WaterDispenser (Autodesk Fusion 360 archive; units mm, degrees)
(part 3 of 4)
sketch "Sketch5" plane through (0, 0, -156.7) normal (0, 0, -1) x axis (-1, 0, 0)
  line L1 (-105.7, 139.3) -> (-100, 139.3)
  line L2 (-105.7, 149.3) -> (-105.7, 139.3)
  line L3 (-100, 149.3) -> (-105.7, 149.3)
  line L4 (-100, 159.3) -> (-100, 149.3)
  line L5 (-105.7, 159.3) -> (-100, 159.3)
  line L6 (-105.7, 169.3) -> (-105.7, 159.3)
  line L7 (-100, 169.3) -> (-105.7, 169.3)
  line L8 (-100, 179.3) -> (-100, 169.3)
  line L9 (-105.7, 179.3) -> (-100, 179.3)
  line L10 (-105.7, 189.3) -> (-105.7, 179.3)
  line L11 (-100, 189.3) -> (-105.7, 189.3)
  line L12 (-100, 199.3) -> (-100, 189.3)
  line L13 (-105.7, 199.3) -> (-100, 199.3)
  line L14 (-105.7, 209.3) -> (-105.7, 199.3)
  line L15 (-100, 209.3) -> (-105.7, 209.3)
  line L16 (-100, 219.3) -> (-100, 209.3)
  line L17 (-105.7, 219.3) -> (-100, 219.3)
  line L18 (-105.7, 229.3) -> (-105.7, 219.3)
  line L19 (-100, 229.3) -> (-105.7, 229.3)
  line L20 (-100, 245) -> (-100, 229.3)
  line L21 (-121, 245) -> (-100, 245)
  line L22 (-121, 239.3) -> (-121, 245)
  line L23 (-131, 239.3) -> (-121, 239.3)
  line L24 (-131, 245) -> (-131, 239.3)
  line L25 (-141, 245) -> (-131, 245)
  line L26 (-141, 239.3) -> (-141, 245)
  line L27 (-151, 239.3) -> (-141, 239.3)
  line L28 (-151, 245) -> (-151, 239.3)
  line L29 (-161, 245) -> (-151, 245)
  line L30 (-161, 239.3) -> (-161, 245)
  line L31 (-171, 239.3) -> (-161, 239.3)
  line L32 (-171, 245) -> (-171, 239.3)
  line L33 (-181, 245) -> (-171, 245)
  line L34 (-181, 239.3) -> (-181, 245)
  line L35 (-191, 239.3) -> (-181, 239.3)
  line L36 (-191, 245) -> (-191, 239.3)
  line L37 (-201, 245) -> (-191, 245)
  line L38 (-201, 230) -> (-201, 245)
  line L39 (-206.7, 230) -> (-201, 230)
  line L40 (-206.7, 220) -> (-206.7, 230)
  line L41 (-201, 220) -> (-206.7, 220)
  line L42 (-201, 210) -> (-201, 220)
  line L43 (-206.7, 210) -> (-201, 210)
  line L44 (-206.7, 200) -> (-206.7, 210)
  line L45 (-201, 200) -> (-206.7, 200)
  line L46 (-201, 190) -> (-201, 200)
  line L47 (-206.7, 190) -> (-201, 190)
  line L48 (-206.7, 180) -> (-206.7, 190)
  line L49 (-201, 180) -> (-206.7, 180)
  line L50 (-201, 170) -> (-201, 180)
  line L51 (-206.7, 170) -> (-201, 170)
  line L52 (-206.7, 160) -> (-206.7, 170)
  line L53 (-201, 160) -> (-206.7, 160)
  line L54 (-201, 150) -> (-201, 160)
  line L55 (-206.7, 150) -> (-201, 150)
  line L56 (-206.7, 140) -> (-206.7, 150)
  line L57 (-201, 140) -> (-206.7, 140)
  line L58 (-201, 130) -> (-201, 140)
  line L59 (-206.7, 130) -> (-201, 130)
  line L60 (-206.7, 120) -> (-206.7, 130)
  line L61 (-201, 120) -> (-206.7, 120)
  line L62 (-201, 110) -> (-201, 120)
  line L63 (-206.7, 110) -> (-201, 110)
  line L64 (-206.7, 100) -> (-206.7, 110)
  line L65 (-201, 100) -> (-206.7, 100)
  line L66 (-201, 90) -> (-201, 100)
  line L67 (-206.7, 90) -> (-201, 90)
  line L68 (-206.7, 80) -> (-206.7, 90)
  line L69 (-201, 80) -> (-206.7, 80)
  line L70 (-201, 70) -> (-201, 80)
  line L71 (-206.7, 70) -> (-201, 70)
  line L72 (-206.7, 60) -> (-206.7, 70)
  line L73 (-201, 60) -> (-206.7, 60)
  line L74 (-201, 50) -> (-201, 60)
  line L75 (-206.7, 50) -> (-201, 50)
  line L76 (-206.7, 40) -> (-206.7, 50)
  line L77 (-201, 40) -> (-206.7, 40)
  line L78 (-201, 30) -> (-201, 40)
  line L79 (-206.7, 30) -> (-201, 30)
  line L80 (-206.7, 20) -> (-206.7, 30)
  line L81 (-201, 20) -> (-206.7, 20)
  line L82 (-201, 10) -> (-201, 20)
  line L83 (-206.7, 10) -> (-201, 10)
  line L84 (-206.7, -5.7) -> (-206.7, 10)
  line L85 (-199, -5.7) -> (-206.7, -5.7)
  line L86 (-199, 0) -> (-199, -5.7)
  line L87 (-189, 0) -> (-199, 0)
  line L88 (-189, -5.7) -> (-189, 0)
  line L89 (-179, -5.7) -> (-189, -5.7)
  line L90 (-179, 0) -> (-179, -5.7)
  line L91 (-169, 0) -> (-179, 0)
  line L92 (-169, -5.7) -> (-169, 0)
  line L93 (-159, -5.7) -> (-169, -5.7)
  line L94 (-159, 0) -> (-159, -5.7)
  line L95 (-149, 0) -> (-159, 0)
  line L96 (-149, -5.7) -> (-149, 0)
  line L97 (-139, -5.7) -> (-149, -5.7)
  line L98 (-139, 0) -> (-139, -5.7)
  line L99 (-129, 0) -> (-139, 0)
  line L100 (-129, -5.7) -> (-129, 0)
  line L101 (-119, -5.7) -> (-129, -5.7)
  line L102 (-119, 0) -> (-119, -5.7)
  line L103 (-109, 0) -> (-119, 0)
  line L104 (-109, -5.7) -> (-109, 0)
  line L105 (-99, -5.7) -> (-109, -5.7)
  line L106 (-99, 0) -> (-99, -5.7)
  line L107 (-89, 0) -> (-99, 0)
  line L108 (-89, -5.7) -> (-89, 0)
  line L109 (-79, -5.7) -> (-89, -5.7)
  line L110 (-79, 0) -> (-79, -5.7)
  line L111 (-69, 0) -> (-79, 0)
  line L112 (-69, -5.7) -> (-69, 0)
  line L113 (-59, -5.7) -> (-69, -5.7)
  line L114 (-59, 0) -> (-59, -5.7)
  line L115 (-49, 0) -> (-59, 0)
  line L116 (-49, -5.7) -> (-49, 0)
  line L117 (-39, -5.7) -> (-49, -5.7)
  line L118 (-39, 0) -> (-39, -5.7)
  line L119 (-29, 0) -> (-39, 0)
  line L120 (-29, -5.7) -> (-29, 0)
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extrude "Extrude9" cut sketch "Sketch5" to an object
sketch "Sketch3" plane through (206.7, 0, 0) normal (1, 0, 0) x axis (0, 0, -1)
  line L1 (59, -5.7) -> (59, 0)
  line L2 (69, -5.7) -> (59, -5.7)
  line L3 (69, 0) -> (69, -5.7)
  line L4 (75, 0) -> (69, 0)
  line L5 (75, 239.3) -> (75, 0)
  line L6 (69, 239.3) -> (75, 239.3)
  line L7 (69, 245) -> (69, 239.3)
  line L8 (59, 245) -> (69, 245)
  line L9 (59, 239.3) -> (59, 245)
  line L10 (49, 239.3) -> (59, 239.3)
  line L11 (49, 245) -> (49, 239.3)
  line L12 (39, 245) -> (49, 245)
  line L13 (39, 239.3) -> (39, 245)
  line L14 (29, 239.3) -> (39, 239.3)
  line L15 (29, 245) -> (29, 239.3)
  line L16 (19, 245) -> (29, 245)
  line L17 (19, 239.3) -> (19, 245)
  line L18 (9, 239.3) -> (19, 239.3)
  line L19 (9, 245) -> (9, 239.3)
  line L20 (-6.7, 245) -> (9, 245)
  line L21 (-6.7, 230) -> (-6.7, 245)
  line L22 (-1, 230) -> (-6.7, 230)
  line L23 (-1, 220) -> (-1, 230)
  line L24 (-6.7, 220) -> (-1, 220)
  line L25 (-6.7, 210) -> (-6.7, 220)
  line L26 (-1, 210) -> (-6.7, 210)
  line L27 (-1, 200) -> (-1, 210)
  line L28 (-6.7, 200) -> (-1, 200)
  line L29 (-6.7, 190) -> (-6.7, 200)
  line L30 (-1, 190) -> (-6.7, 190)
  line L31 (-1, 180) -> (-1, 190)
  line L32 (-6.7, 180) -> (-1, 180)
  line L33 (-6.7, 170) -> (-6.7, 180)
  line L34 (-1, 170) -> (-6.7, 170)
  line L35 (-1, 160) -> (-1, 170)
  line L36 (-6.7, 160) -> (-1, 160)
  line L37 (-6.7, 150) -> (-6.7, 160)
  line L38 (-1, 150) -> (-6.7, 150)
  line L39 (-1, 140) -> (-1, 150)
  line L40 (-6.7, 140) -> (-1, 140)
  line L41 (-6.7, 130) -> (-6.7, 140)
  line L42 (-1, 130) -> (-6.7, 130)
  line L43 (-1, 120) -> (-1, 130)
  line L44 (-6.7, 120) -> (-1, 120)
  line L45 (-6.7, 110) -> (-6.7, 120)
  line L46 (-1, 110) -> (-6.7, 110)
  line L47 (-1, 100) -> (-1, 110)
  line L48 (-6.7, 100) -> (-1, 100)
  line L49 (-6.7, 90) -> (-6.7, 100)
  line L50 (-1, 90) -> (-6.7, 90)
  line L51 (-1, 80) -> (-1, 90)
  line L52 (-6.7, 80) -> (-1, 80)
  line L53 (-6.7, 70) -> (-6.7, 80)
  line L54 (-1, 70) -> (-6.7, 70)
  line L55 (-1, 60) -> (-1, 70)
  line L56 (-6.7, 60) -> (-1, 60)
  line L57 (-6.7, 50) -> (-6.7, 60)
  line L58 (-1, 50) -> (-6.7, 50)
  line L59 (-1, 40) -> (-1, 50)
  line L60 (-6.7, 40) -> (-1, 40)
  line L61 (-6.7, 30) -> (-6.7, 40)
  line L62 (-1, 30) -> (-6.7, 30)
  line L63 (-1, 20) -> (-1, 30)
  line L64 (-6.7, 20) -> (-1, 20)
  line L65 (-6.7, 10) -> (-6.7, 20)
  line L66 (-1, 10) -> (-6.7, 10)
  line L67 (-1, -5.7) -> (-1, 10)
  line L68 (9, -5.7) -> (-1, -5.7)
  line L69 (9, 0) -> (9, -5.7)
  line L70 (19, 0) -> (9, 0)
  line L71 (19, -5.7) -> (19, 0)
  line L72 (29, -5.7) -> (19, -5.7)
  line L73 (29, 0) -> (29, -5.7)
  line L74 (39, 0) -> (29, 0)
  line L75 (39, -5.7) -> (39, 0)
  line L76 (49, -5.7) -> (39, -5.7)
  line L77 (49, 0) -> (49, -5.7)
  line L78 (59, 0) -> (49, 0)
  line L79 (18.25, 199.3) -> (18.25, 205)
  line L80 (43.25, 199.3) -> (18.25, 199.3)
  line L81 (43.25, 205) -> (43.25, 199.3)
  line L82 (18.25, 205) -> (43.25, 205)
  line L83 (62.5, 199.3) -> (62.5, 205)
  line L84 (75, 199.3) -> (62.5, 199.3)
  line L85 (75, 205) -> (75, 199.3)
  line L86 (62.5, 205) -> (75, 205)
  line L87 (87.5, 205) -> (87.5, 199.3)
  line L88 (75, 205) -> (87.5, 205)
  line L89 (75, 199.3) -> (75, 205)
  line L90 (87.5, 199.3) -> (75, 199.3)
  line L91 (131.75, 205) -> (131.75, 199.3)
  line L92 (106.75, 205) -> (131.75, 205)
  line L93 (106.75, 199.3) -> (106.75, 205)
  line L94 (131.75, 199.3) -> (106.75, 199.3)
extrude "Extrude3" cut sketch "Sketch3" profile of L5 L79 L80 L81 L82 L83 L84 L85 L86 L87 L88 L89 L90 L91 L92 L93 L94 to an object
sketch "Sketch6" plane through (0, 199.3, 0) normal (0, -1, 0) x axis (1, 0, 0)
  line L1 (164.675, -156.7) -> (164.675, -151)
  line L2 (189.675, -156.7) -> (164.675, -156.7)
  line L3 (189.675, -151) -> (189.675, -156.7)
  line L4 (201, -151) -> (189.675, -151)
  line L5 (201, -131.75) -> (201, -151)
  line L6 (206.7, -131.75) -> (201, -131.75)
  line L7 (206.7, -106.75) -> (206.7, -131.75)
  line L8 (201, -106.75) -> (206.7, -106.75)
  line L9 (201, -87.5) -> (201, -106.75)
  line L10 (206.7, -87.5) -> (201, -87.5)
  line L11 (206.7, -75) -> (206.7, -87.5)
  line L12 (105.7, -75) -> (206.7, -75)
  line L13 (105.7, -151) -> (105.7, -75)
  line L14 (164.675, -151) -> (105.7, -151)
  circle C1 centre (187.05, -137.05) radius 4.95
sketch "Sketch4" plane through (0, 199.3, 0) normal (0, -1, 0) x axis (1, 0, 0)
  line L1 (164.675, -156.7) -> (164.675, -151)
  line L2 (189.675, -156.7) -> (164.675, -156.7)
  line L3 (189.675, -151) -> (189.675, -156.7)
  line L4 (201, -151) -> (189.675, -151)
  line L5 (201, -131.75) -> (201, -151)
  line L6 (206.7, -131.75) -> (201, -131.75)
  line L7 (206.7, -106.75) -> (206.7, -131.75)
  line L8 (201, -106.75) -> (206.7, -106.75)
  line L9 (201, -87.5) -> (201, -106.75)
  line L10 (206.7, -87.5) -> (201, -87.5)
  line L11 (206.7, -75) -> (206.7, -87.5)
  line L12 (105.7, -75) -> (206.7, -75)
  line L13 (105.7, -151) -> (105.7, -75)
  line L14 (164.675, -151) -> (105.7, -151)
  circle C1 centre (187.05, -137.05) radius 4.95
extrude "Extrude3" cut sketch "Sketch4" profile of C1 to an object
sketch "Sketch7" plane through (195, 0, 0) normal (-1, 0, 0) x axis (0, 0, 1)
  line L1 (-137.05, 35) -> (-126, 35)
  line L2 (-145, 35) -> (-137.05, 35)
  line L3 (-145, 0) -> (-145, 35)
  line L4 (-5, 0) -> (-145, 0)
  line L5 (-5, 15) -> (-5, 0)
  line L6 (-126, 15) -> (-5, 15)
  line L7 (-126, 35) -> (-126, 15)
  line L8 (-126, 15) -> (-5, 15)
  line L9 (-145, 0) -> (-5, 0)
  line L10 (-5, 15) -> (-5, 0)
  line L11 (-25, 0) -> (-25, 15)
  circle C1 centre (-25, 7.5) radius 5
  point P13 (-25, 15)
  point P15 (-25, 7.5)
  point P14 (-25, 0)
  vertical L11
  coincident L8 P13
  midpoint L11 P15
  dimension "d360" distance P13 P14 = 15
  dimension "d363" distance L5 L11 = 20 (= "AcDistanceHole")
  dimension "d364" diameter C1 = 10 (= "AcHoleDiameter")
extrude "Extrude17" cut sketch "Sketch7" profile of L11 C1 against normal blind 11.7
combine "Combine4"
chamfer "Chamfer6" distance 8 distance 6
fillet "Fillet22" radius 2
sketch "Sketch14" plane through (0, 0, 0) normal (0, -1, 0) x axis (1, 0, 0)
  line L1 (0, -150) -> (0, 0)
  line L2 (200, -150) -> (0, -150)
  line L3 (200, 0) -> (200, -150)
  line L4 (0, 0) -> (200, 0)
  line L5 (195, -5) -> (5, -5)
  line L6 (195, -145) -> (195, -5)
  line L7 (5, -145) -> (195, -145)
  line L8 (5, -5) -> (5, -145)
  circle C1 centre (0, -150) radius 15
  circle C2 centre (0, 0) radius 15
  circle C3 centre (200, 0) radius 15
  circle C4 centre (200, -150) radius 15
  point P3 (0, -150)
  point P10 (0, -150)
  point P1 (0, 0)
  point P11 (0, 0)
  point P5 (200, 0)
  point P12 (200, 0)
  point P4 (200, -150)
  point P13 (200, -150)
  coincident P3 P10
  coincident P1 P11
  coincident P5 P12
  coincident P4 P13
  dimension "d374" diameter C1 = 30
  dimension "d375" diameter C2 = 30
  dimension "d376" diameter C3 = 30
  dimension "d377" diameter C4 = 30
extrude "Extrude18" add sketch "Sketch14" profile of L1 L2 L3 L4 C1 C2 C3 C4 against normal blind 0.5
sketch "Sketch15" plane through (106.7, 0, 0) normal (-1, 0, 0) x axis (0, 0, 1)
  line L1 (-67.8211, 215.1129) -> (-70.3015, 214.2101)
  curve K1 (-64.4934, 215.3409) -> (-67.8211, 215.1129)
  curve K2 (-64.4934, 215.3409) -> (-66.5703, 205)
  line L2 (0, 205) -> (-66.5703, 205)
  line L3 (0, 238.3) -> (0, 205)
  line L4 (-150, 238.3) -> (0, 238.3)
  line L5 (-150, 205) -> (-150, 238.3)
  line L6 (-83.4297, 205) -> (-150, 205)
  curve K3 (-83.4297, 205) -> (-85.5066, 215.3409)
  curve K4 (-82.1789, 215.1129) -> (-85.5066, 215.3409)
  line L7 (-79.6985, 214.2101) -> (-82.1789, 215.1129)
  line L8 (0, 223.3) -> (-150, 223.3)
  line L9 (-100, 205) -> (-100, 238.3)
  line L10 (-75, 210) -> (-75, 238.3)
  arc A1 centre (-75, 212.5) radius 5 clockwise from (-79.6985, 214.2101) to (-70.3015, 214.2101)
  circle C1 centre (-100, 223.3) radius 4
  circle C2 centre (-100, 223.3) radius 5.5
  point P16 (-150, 223.3)
  point P17 (0, 223.3)
  point P18 (-100, 238.3)
  point P19 (-100, 205)
  point P22 (-100, 223.3)
  coincident L5 P16
  coincident L3 P17
  perpendicular L3 L8
  coincident L4 P18
  coincident L6 P19
  perpendicular L6 L9
  coincident L8 P22
  coincident L9 P22
  concentric C1 C2
  dimension "d380" distance L4 L8 = 15
  dimension "d381" distance L9 L10 = 25
  dimension "d382" diameter C1 = 8
  dimension "d383" diameter C2 = 11
work_plane "WorkPlane4" AlongDistance -100
sketch "Sketch16" plane through (153.35, 221.65, -100) normal (0, 0, 1) x axis (1, 0, 0)
  line L1 (-46.65, -7.4399) -> (-46.65, -4.15)
  line L2 (-46.65, -6.5371) -> (-46.65, -7.4399)
  line L3 (-46.65, -6.25) -> (-46.65, -6.5371)
  line L4 (-46.65, -6.3091) -> (-46.65, -16.65)
  line L5 (-46.65, 16.65) -> (-46.65, -16.65)
  line L6 (-46.65, -16.65) -> (-46.65, 16.65)
  line L7 (-46.65, -16.65) -> (-46.65, -6.3091)
  line L8 (-46.65, -6.5371) -> (-46.65, -6.25)
  line L9 (-46.65, -7.4399) -> (-46.65, -6.5371)
  line L10 (-41.65, -4.15) -> (-41.65, -7.65)
  line L11 (-41.65, 16.65) -> (-41.65, -7.65)
  line L12 (-41.65, -7.65) -> (-41.65, 16.65)
  line L13 (37.65, -11.65) -> (36.65, -11.65)
  line L14 (37.65, -11.65) -> (20.7504, -11.65)
  line L15 (-36.65, -11.65) -> (21.4562, -11.65)
  line L16 (-36.65, -11.65) -> (-37.65, -11.65)
  line L17 (-31.65, -11.65) -> (-37.65, -11.65)
  line L18 (-30.3271, -11.65) -> (-31.65, -11.65)
  line L19 (-37.65, -11.65) -> (-31.65, -11.65)
  line L20 (-36.65, -11.65) -> (-37.65, -11.65)
  line L21 (36.65, -11.65) -> (-36.65, -11.65)
  line L22 (-46.65, 16.65) -> (46.65, 16.65)
  line L23 (38.65, -16.65) -> (28.75, -16.65)
  line L24 (-48.571, -16.65) -> (-46.65, -16.65)
  line L25 (46.65, -16.65) -> (-46.65, -16.65)
  line L26 (-46.65, -16.65) -> (46.65, -16.65)
  curve K1 (-41.65, -7.65) -> (-38.7422, -11.498)
  line L27 (-41.65, 1.65) -> (-46.65, 1.65)
  curve K2 (-29, 1) -> (-41.65, 1.65)
  curve K3 (-30.65, -21) -> (-29, 1)
  curve K4 (-30.65, -21) -> (-41.65, 1.65)
  arc A1 centre (-37.65, -7.65) radius 4 clockwise from (-37.65, -11.65) to (-38.7422, -11.498)
  arc A2 centre (-37.65, -7.65) radius 4 clockwise from (-37.65, -11.65) to (-41.65, -7.65)
  point P33 (-46.65, 1.65)
  point P34 (-46.65, 1.65)
  point P35 (-41.65, 1.65)
  horizontal L27
  coincident P33 P34
  dimension "d385" distance P34 P35 = 5
sweep "Sweep4" sketch "Sketch15" TwistAngle 0 TaperAngle 0
sweep "Sweep5" sketch "Sketch15" TwistAngle 0 TaperAngle 0
sketch "Sketch17" plane through (46.65, 205, -153.85) normal (0, 1, 0) x axis (1, 0, 0)
  line L1 (104.8624, -146.625) -> (59.7851, -146.625)
  line L2 (104.8624, -7.6838) -> (104.8624, -146.625)
  line L3 (59.7851, -7.6838) -> (104.8624, -7.6838)
  line L4 (59.7851, -146.625) -> (59.7851, -7.6838)
  horizontal L1
  vertical L2
  horizontal L3
  vertical L4
extrude "Extrude7" cut sketch "Sketch17" against normal blind 10
fillet "Fillet15" radius 1
fillet "Fillet23" radius 3
sketch "Sketch18" plane through (153.35, 221.65, -75) normal (0, 0, 1) x axis (1, 0, 0)
sketch "Sketch19" plane through (46.65, 205, -153.85) normal (0, 1, 0) x axis (1, 0, 0)
  line L1 (60.05, -3.85) -> (60.05, -153.85)
  line L2 (60.05, -153.85) -> (60.05, -3.85)
  line L3 (60.05, -153.85) -> (153.35, -153.85)
  line L4 (153.35, -153.85) -> (153.35, -3.85)
  line L5 (153.35, -3.85) -> (60.05, -3.85)
  circle C1 centre (60.05, -153.85) radius 15
  circle C2 centre (153.35, -153.85) radius 15
  circle C3 centre (60.05, -3.85) radius 15
  circle C4 centre (154.35, -2.85) radius 15
  point P4 (60.05, -153.85)
  point P8 (60.05, -153.85)
  point P5 (153.35, -153.85)
  point P9 (153.35, -153.85)
  point P3 (60.05, -3.85)
  point P10 (60.05, -3.85)
  point P6 (154.35, -2.85)
  point P11 (154.35, -2.85)
  coincident P4 P8
  coincident P5 P9
  coincident P3 P10
  coincident P6 P11
  dimension "d403" diameter C1 = 30
  dimension "d404" diameter C2 = 30
  dimension "d405" diameter C3 = 30
  dimension "d406" diameter C4 = 30
extrude "Extrude8" add sketch "Sketch19" along normal blind 0.5
fillet "Fillet16" radius 2
sketch "Sketch6" plane through (100, 0, 0) normal (-1, 0, 0) x axis (0, 0, 1)
  line L1 (-75, 214.3397) -> (-82.2709, 214.3397)
  line L2 (-75, 239.3) -> (-75, 214.3397)
  line L3 (-81, 239.3) -> (-75, 239.3)
  line L4 (-81, 245) -> (-81, 239.3)
  line L5 (-91, 245) -> (-81, 245)
  line L6 (-91, 239.3) -> (-91, 245)
  line L7 (-101, 239.3) -> (-91, 239.3)
  line L8 (-101, 245) -> (-101, 239.3)
  line L9 (-111, 245) -> (-101, 245)
  line L10 (-111, 239.3) -> (-111, 245)
  line L11 (-121, 239.3) -> (-111, 239.3)
  line L12 (-121, 245) -> (-121, 239.3)
  line L13 (-131, 245) -> (-121, 245)
  line L14 (-131, 239.3) -> (-131, 245)
  line L15 (-141, 239.3) -> (-131, 239.3)
  line L16 (-141, 245) -> (-141, 239.3)
  line L17 (-151, 245) -> (-141, 245)
  line L18 (-151, 229.3) -> (-151, 245)
  line L19 (-156.7, 229.3) -> (-151, 229.3)
  line L20 (-156.7, 219.3) -> (-156.7, 229.3)
  line L21 (-151, 219.3) -> (-156.7, 219.3)
  line L22 (-151, 209.3) -> (-151, 219.3)
  line L23 (-156.7, 209.3) -> (-151, 209.3)
  line L24 (-156.7, 199.3) -> (-156.7, 209.3)
  line L25 (-151, 199.3) -> (-156.7, 199.3)
  line L26 (-151, 189.3) -> (-151, 199.3)
  line L27 (-156.7, 189.3) -> (-151, 189.3)
  line L28 (-156.7, 179.3) -> (-156.7, 189.3)
  line L29 (-151, 179.3) -> (-156.7, 179.3)
  line L30 (-151, 169.3) -> (-151, 179.3)
  line L31 (-156.7, 169.3) -> (-151, 169.3)
  line L32 (-156.7, 159.3) -> (-156.7, 169.3)
  line L33 (-151, 159.3) -> (-156.7, 159.3)
  line L34 (-151, 149.3) -> (-151, 159.3)
  line L35 (-156.7, 149.3) -> (-151, 149.3)
  line L36 (-156.7, 139.3) -> (-156.7, 149.3)
  line L37 (-151, 139.3) -> (-156.7, 139.3)
  line L38 (-151, 129.3) -> (-151, 139.3)
  line L39 (-156.7, 129.3) -> (-151, 129.3)
  line L40 (-156.7, 119.3) -> (-156.7, 129.3)
  line L41 (-151, 119.3) -> (-156.7, 119.3)
  line L42 (-151, 109.3) -> (-151, 119.3)
  line L43 (-156.7, 109.3) -> (-151, 109.3)
  line L44 (-156.7, 99.3) -> (-156.7, 109.3)
  line L45 (-151, 99.3) -> (-156.7, 99.3)
  line L46 (-151, 85) -> (-151, 99.3)
  line L47 (-75, 85) -> (-151, 85)
  line L48 (-75, 205) -> (-75, 85)
  arc A1 centre (-75, 212.5) radius 7.5 clockwise from (-75, 205) to (-82.2709, 214.3397)
  circle C1 centre (-100, 223.3) radius 4
extrude "Extrude4" cut sketch "Sketch6" profile of C1 to an object
sketch "Sketch7" plane through (100, 0, 0) normal (-1, 0, 0) x axis (0, 0, 1)
  line L1 (-67.7291, 214.3397) -> (-75, 214.3397)
  line L2 (-75, 85) -> (-75, 205)
  line L3 (1, 85) -> (-75, 85)
  line L4 (1, 99.3) -> (1, 85)
  line L5 (6.7, 99.3) -> (1, 99.3)
  line L6 (6.7, 109.3) -> (6.7, 99.3)
  line L7 (1, 109.3) -> (6.7, 109.3)
  line L8 (1, 119.3) -> (1, 109.3)
  line L9 (6.7, 119.3) -> (1, 119.3)
  line L10 (6.7, 129.3) -> (6.7, 119.3)
  line L11 (1, 129.3) -> (6.7, 129.3)
  line L12 (1, 139.3) -> (1, 129.3)
  line L13 (6.7, 139.3) -> (1, 139.3)
  line L14 (6.7, 149.3) -> (6.7, 139.3)
  line L15 (1, 149.3) -> (6.7, 149.3)
  line L16 (1, 159.3) -> (1, 149.3)
  line L17 (6.7, 159.3) -> (1, 159.3)
  line L18 (6.7, 169.3) -> (6.7, 159.3)
  line L19 (1, 169.3) -> (6.7, 169.3)
  line L20 (1, 179.3) -> (1, 169.3)
  line L21 (6.7, 179.3) -> (1, 179.3)
  line L22 (6.7, 189.3) -> (6.7, 179.3)
  line L23 (1, 189.3) -> (6.7, 189.3)
  line L24 (1, 199.3) -> (1, 189.3)
  line L25 (6.7, 199.3) -> (1, 199.3)
  line L26 (6.7, 209.3) -> (6.7, 199.3)
  line L27 (1, 209.3) -> (6.7, 209.3)
  line L28 (1, 219.3) -> (1, 209.3)
  line L29 (6.7, 219.3) -> (1, 219.3)
  line L30 (6.7, 229.3) -> (6.7, 219.3)
  line L31 (1, 229.3) -> (6.7, 229.3)
  line L32 (1, 245) -> (1, 229.3)
  line L33 (-9, 245) -> (1, 245)
  line L34 (-9, 239.3) -> (-9, 245)
  line L35 (-19, 239.3) -> (-9, 239.3)
  line L36 (-19, 245) -> (-19, 239.3)
  line L37 (-29, 245) -> (-19, 245)
  line L38 (-29, 239.3) -> (-29, 245)
  line L39 (-39, 239.3) -> (-29, 239.3)
  line L40 (-39, 245) -> (-39, 239.3)
  line L41 (-49, 245) -> (-39, 245)
  line L42 (-49, 239.3) -> (-49, 245)
  line L43 (-59, 239.3) -> (-49, 239.3)
  line L44 (-59, 245) -> (-59, 239.3)
  line L45 (-69, 245) -> (-59, 245)
  line L46 (-69, 239.3) -> (-69, 245)
  line L47 (-75, 239.3) -> (-69, 239.3)
  line L48 (-75, 214.3397) -> (-75, 239.3)
  line L49 (-75, 214.3397) -> (-82.2709, 214.3397)
  line L50 (-75, 239.3) -> (-75, 214.3397)
  line L51 (-81, 239.3) -> (-75, 239.3)
  line L52 (-81, 245) -> (-81, 239.3)
  line L53 (-91, 245) -> (-81, 245)
  line L54 (-91, 239.3) -> (-91, 245)
  line L55 (-101, 239.3) -> (-91, 239.3)
  line L56 (-101, 245) -> (-101, 239.3)
  line L57 (-111, 245) -> (-101, 245)
  line L58 (-111, 239.3) -> (-111, 245)
  line L59 (-121, 239.3) -> (-111, 239.3)
  line L60 (-121, 245) -> (-121, 239.3)
  line L61 (-131, 245) -> (-121, 245)
  line L62 (-131, 239.3) -> (-131, 245)
  line L63 (-141, 239.3) -> (-131, 239.3)
  line L64 (-141, 245) -> (-141, 239.3)
  line L65 (-151, 245) -> (-141, 245)
  line L66 (-151, 229.3) -> (-151, 245)
  line L67 (-156.7, 229.3) -> (-151, 229.3)
  line L68 (-156.7, 219.3) -> (-156.7, 229.3)
  line L69 (-151, 219.3) -> (-156.7, 219.3)
  line L70 (-151, 209.3) -> (-151, 219.3)
  line L71 (-156.7, 209.3) -> (-151, 209.3)
  line L72 (-156.7, 199.3) -> (-156.7, 209.3)
  line L73 (-151, 199.3) -> (-156.7, 199.3)
  line L74 (-151, 189.3) -> (-151, 199.3)
  line L75 (-156.7, 189.3) -> (-151, 189.3)
  line L76 (-156.7, 179.3) -> (-156.7, 189.3)
  line L77 (-151, 179.3) -> (-156.7, 179.3)
  line L78 (-151, 169.3) -> (-151, 179.3)
  line L79 (-156.7, 169.3) -> (-151, 169.3)
  line L80 (-156.7, 159.3) -> (-156.7, 169.3)
  line L81 (-151, 159.3) -> (-156.7, 159.3)
  line L82 (-151, 149.3) -> (-151, 159.3)
  line L83 (-156.7, 149.3) -> (-151, 149.3)
  line L84 (-156.7, 139.3) -> (-156.7, 149.3)
  line L85 (-151, 139.3) -> (-156.7, 139.3)
  line L86 (-151, 129.3) -> (-151, 139.3)
  line L87 (-156.7, 129.3) -> (-151, 129.3)
  line L88 (-156.7, 119.3) -> (-156.7, 129.3)
  line L89 (-151, 119.3) -> (-156.7, 119.3)
  line L90 (-151, 109.3) -> (-151, 119.3)
  line L91 (-156.7, 109.3) -> (-151, 109.3)
  line L92 (-156.7, 99.3) -> (-156.7, 109.3)
  line L93 (-151, 99.3) -> (-156.7, 99.3)
  line L94 (-151, 85) -> (-151, 99.3)
  line L95 (-75, 85) -> (-151, 85)
  line L96 (-75, 205) -> (-75, 85)
  line L97 (-30, 205) -> (-143.23, 205)
  line L98 (-20, 165) -> (-141, 165)
  line L99 (-150, 85) -> (0, 85)
  arc A1 centre (-75, 212.5) radius 7.5 clockwise from (-67.7291, 214.3397) to (-75, 205)
  circle C1 centre (-100, 223.3) radius 4
  arc A2 centre (-75, 212.5) radius 7.5 clockwise from (-75, 205) to (-82.2709, 214.3397)
  circle C2 centre (-75, 165) radius 4
  point P109 (-75, 165)
  perpendicular L96 L97
  tangent A1 L97
  perpendicular L96 L98
  coincident L98 P109
  coincident L96 P109
  dimension "d412" distance L98 L99 = 80
  dimension "d413" diameter C2 = 8
extrude "Extrude5" cut sketch "Sketch7" profile of L2 L96 C2 to an object
external_derived "ExternalDerived1"
external_derived "ExternalDerived2"
external_derived "ExternalDerived3"
derived_instance "DerivedInstance1"
position "Position1"
sketch "Sketch4" plane through (206.7, 0, 0) normal (1, 0, 0) x axis (0, 0, -1)
  line L1 (75, 205) -> (62.5, 205)
  line L2 (75, 239.3) -> (75, 205)
  line L3 (69, 239.3) -> (75, 239.3)
  line L4 (69, 245) -> (69, 239.3)
  line L5 (59, 245) -> (69, 245)
  line L6 (59, 239.3) -> (59, 245)
  line L7 (49, 239.3) -> (59, 239.3)
  line L8 (49, 245) -> (49, 239.3)
  line L9 (39, 245) -> (49, 245)
  line L10 (39, 239.3) -> (39, 245)
  line L11 (29, 239.3) -> (39, 239.3)
  line L12 (29, 245) -> (29, 239.3)
  line L13 (19, 245) -> (29, 245)
  line L14 (19, 239.3) -> (19, 245)
  line L15 (9, 239.3) -> (19, 239.3)
  line L16 (9, 245) -> (9, 239.3)
  line L17 (-6.7, 245) -> (9, 245)
  line L18 (-6.7, 230) -> (-6.7, 245)
  line L19 (-1, 230) -> (-6.7, 230)
  line L20 (-1, 220) -> (-1, 230)
  line L21 (-6.7, 220) -> (-1, 220)
  line L22 (-6.7, 210) -> (-6.7, 220)
  line L23 (-1, 210) -> (-6.7, 210)
  line L24 (-1, 200) -> (-1, 210)
  line L25 (-6.7, 200) -> (-1, 200)
  line L26 (-6.7, 190) -> (-6.7, 200)
  line L27 (-1, 190) -> (-6.7, 190)
  line L28 (-1, 180) -> (-1, 190)
  line L29 (-6.7, 180) -> (-1, 180)
  line L30 (-6.7, 170) -> (-6.7, 180)
  line L31 (-1, 170) -> (-6.7, 170)
  line L32 (-1, 160) -> (-1, 170)
  line L33 (-6.7, 160) -> (-1, 160)
  line L34 (-6.7, 150) -> (-6.7, 160)
  line L35 (-1, 150) -> (-6.7, 150)
  line L36 (-1, 140) -> (-1, 150)
  line L37 (-6.7, 140) -> (-1, 140)
  line L38 (-6.7, 130) -> (-6.7, 140)
  line L39 (-1, 130) -> (-6.7, 130)
  line L40 (-1, 120) -> (-1, 130)
  line L41 (-6.7, 120) -> (-1, 120)
  line L42 (-6.7, 110) -> (-6.7, 120)
  line L43 (-1, 110) -> (-6.7, 110)
  line L44 (-1, 100) -> (-1, 110)
  line L45 (-6.7, 100) -> (-1, 100)
  line L46 (-6.7, 90) -> (-6.7, 100)
  line L47 (-1, 90) -> (-6.7, 90)
  line L48 (-1, 80) -> (-1, 90)
  line L49 (-6.7, 80) -> (-1, 80)
  line L50 (-6.7, 70) -> (-6.7, 80)
  line L51 (-1, 70) -> (-6.7, 70)
  line L52 (-1, 60) -> (-1, 70)
  line L53 (-6.7, 60) -> (-1, 60)
  line L54 (-6.7, 50) -> (-6.7, 60)
  line L55 (-1, 50) -> (-6.7, 50)
  line L56 (-1, 40) -> (-1, 50)
  line L57 (-6.7, 40) -> (-1, 40)
  line L58 (-6.7, 30) -> (-6.7, 40)
  line L59 (-1, 30) -> (-6.7, 30)
  line L60 (-1, 20) -> (-1, 30)
  line L61 (-6.7, 20) -> (-1, 20)
  line L62 (-6.7, 10) -> (-6.7, 20)
  line L63 (-1, 10) -> (-6.7, 10)
  line L64 (-1, -5.7) -> (-1, 10)
  line L65 (9, -5.7) -> (-1, -5.7)
  line L66 (9, 0) -> (9, -5.7)
  line L67 (19, 0) -> (9, 0)
  line L68 (19, -5.7) -> (19, 0)
  line L69 (29, -5.7) -> (19, -5.7)
  line L70 (29, 0) -> (29, -5.7)
  line L71 (39, 0) -> (29, 0)
  line L72 (39, -5.7) -> (39, 0)
  line L73 (49, -5.7) -> (39, -5.7)
  line L74 (49, 0) -> (49, -5.7)
  line L75 (59, 0) -> (49, 0)
  line L76 (59, -5.7) -> (59, 0)
  line L77 (69, -5.7) -> (59, -5.7)
  line L78 (69, 0) -> (69, -5.7)
  line L79 (75, 0) -> (69, 0)
  line L80 (75, 199.3) -> (75, 0)
  line L81 (62.5, 199.3) -> (75, 199.3)
  line L82 (62.5, 205) -> (62.5, 199.3)
  line L83 (43.25, 199.3) -> (43.25, 205)
  line L84 (18.25, 199.3) -> (43.25, 199.3)
  line L85 (18.25, 205) -> (18.25, 199.3)
  line L86 (43.25, 205) -> (18.25, 205)
  line L87 (10, 95) -> (10, 185)
  line L88 (100, 95) -> (10, 95)
  line L89 (100, 185) -> (100, 95)
  line L90 (10, 185) -> (100, 185)
  line L91 (151, 140) -> (151, 150)
  circle C1 centre (25, 7.5) radius 5
  circle C2 centre (50, 101) radius 2
  circle C3 centre (16, 179) radius 2
  circle C4 centre (89, 140) radius 2
  circle C5 centre (89, 101) radius 2
  circle C6 centre (50, 179) radius 2
  circle C7 centre (89, 179) radius 2
  circle C8 centre (16, 101) radius 2
  circle C9 centre (50, 140) radius 28
  circle C10 centre (50, 140) radius 33
  dimension "d418" = 5
extrude "Extrude6" cut sketch "Sketch4" profile of L80 C9 C10 to an object
extrude "Extrude5" cut sketch "Sketch4" profile of C2 C3 C4 C5 C6 C7 C8 to an object
sketch "Sketch8" plane through (0, 199.3, 0) normal (0, -1, 0) x axis (1, 0, 0)
  circle C1 centre (122.7, -100) radius 4
  point P2 (122.7, -100)
  point P3 (122.7, -100)
  coincident P2 P3
  dimension "d421" diameter C1 = 8
extrude "Extrude4" cut sketch "Sketch8" against normal blind 5.7
combine "Combine3"
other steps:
derived_base_feature "Sketch1" bodies "Body1"
derived_base_feature "Derived Base Feature1" bodies "Body1"
derived_base_feature "Derived Base Feature2" bodies "Body1 (1)"
extrude "Extrude4" cut sketch "Sketch7" profile of L11 C1 against normal blind 11.7
create_component "CreateComponent1"
create_component "CreateComponent2"
create_component "CreateComponent3"
create_component "CreateComponent1"
create_component "CreateComponent1"
remove_instance "RemoveInstance1"
remove_instance "RemoveInstance1"
create_component "CreateComponent4"
create_component "CreateComponent1"
remove_instance "RemoveInstance1"
create_component "CreateComponent5"
create_component "CreateComponent1"
remove_instance "RemoveInstance1"
create_component "CreateComponent6"
named bodies: "Body1", "Body1 (1)"

design "Pump"
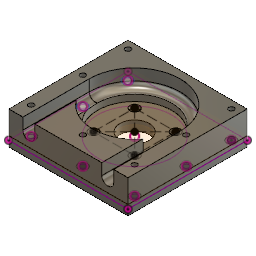
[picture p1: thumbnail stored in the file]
parameter "InDiameterBearing" = 8
parameter "OutDiameterBearing" = 22
parameter "BearingHolderDiameter" = 55
parameter "BearingHeight" = 7.5
parameter "BearingOffset" = 7
parameter "BaseThickness" = 6
parameter "BearingGap" = 1
parameter "TopThickness" = 3
parameter "TubeDiameter" = 9
parameter "TubeOffset" = 2
parameter "PumpTopDistance" = 40
parameter "PumpWidth" = 90
parameter "PumpBottomDistance" = 50
parameter "TubeLengthOutput" = 70
parameter "MotorDiameterHeight" = 3
parameter "MotorDiameter" = 22
parameter "ScrewDiameter" = 4
parameter "ScrewHeadDiameter" = 7
parameter "screwHeadHeight" = 4
parameter "ScrewHoleBearingOffset" = 7
parameter "ShaftDiameter" = 5
parameter "ShaftNotchDistance" = 4.55
parameter "ShaftLength" = 13.1 (= "12.6 mm + 0.5 mm")
parameter "GapBeetweenParts" = 1
parameter "DistanceScrewMotor" = 31
parameter "ScrewMotorDiameter" = 3
parameter "ScrewMotorHeadDiameter" = 7
parameter "ScrewMotorHeadHeight" = 2.5
sketch "Sketch1" plane through (0, 0, 0) normal (0, 1, 0) x axis (1, 0, 0)
  circle C1 centre (0, 0) radius 27.5
  point P1 (0, 0)
  point P2 (0, 0)
  coincident P1 P2
  dimension "d4" diameter C1 = 55 (= "BearingHolderDiameter")
extrude "Extrude1" new body sketch "Sketch1" along normal blind 7.5 (= "BearingHeight")
sketch "Sketch2" plane through (0, 7.5, 0) normal (0, 1, 0) x axis (-1, 0, 0)
  line L1 (0, -27.5) -> (0, 0)
  line L2 (23.8157, 13.75) -> (0, 0)
  line L3 (-23.8157, 13.75) -> (0, 0)
  circle C1 centre (0, 0) radius 27.5
  circle C2 centre (0, 0) radius 20
  circle C3 centre (0, -20) radius 11.5
  circle C4 centre (-17.3205, 10) radius 11.5
  circle C5 centre (17.3205, 10) radius 11.5
  point P3 (0, 0)
  point P4 (0, 0)
  point P5 (0, -27.5)
  point P10 (0, -20)
  point P11 (-17.3205, 10)
  point P12 (17.3205, 10)
  concentric C1 C2
  coincident P3 P4
  coincident C1 P5
  vertical L1
  coincident C2 P10
  coincident L1 P10
  coincident C2 P11
  coincident L3 P11
  coincident C2 P12
  coincident L2 P12
  dimension "d12" diameter C3 = 23 (= "OutDiameterBearing + BearingGap")
  dimension "d13" diameter C4 = 23 (= "OutDiameterBearing + BearingGap")
  dimension "d14" diameter C5 = 23 (= "OutDiameterBearing + BearingGap")
  dimension "d11" C-Pattern1-Angle = 360
extrude "Extrude2" cut sketch "Sketch2" profile of C1 C3 C4 C5 to an object
extrude "Extrude3" new body sketch "Sketch1" no distance stored
sketch "Sketch3" plane through (0, 0, 0) normal (0, 1, 0) x axis (1, 0, 0)
  circle C1 centre (17.3205, -10) radius 4
  circle C2 centre (-17.3205, -10) radius 4
  circle C3 centre (0, 20) radius 4
  point P2 (17.3205, -10)
  point P5 (17.3205, -10)
  point P3 (-17.3205, -10)
  point P6 (-17.3205, -10)
  point P4 (0, 20)
  point P7 (0, 20)
  coincident P2 P5
  coincident P3 P6
  coincident P4 P7
  dimension "d20" diameter C1 = 8 (= "InDiameterBearing")
  dimension "d21" diameter C2 = 8 (= "InDiameterBearing")
  dimension "d22" diameter C3 = 8 (= "InDiameterBearing")
extrude "Extrude4" new body sketch "Sketch3" along normal blind 10.5 (= "BearingHeight + TopThickness")
sketch "Sketch1" plane through (0, 7.5, 0) normal (0, 1, 0) x axis (-1, 0, 0)
  arc A1 centre (0, -20) radius 11.5 clockwise from (-10.0444, -25.6) to (10.0444, -25.6)
  arc A2 centre (0, 0) radius 27.5 clockwise from (27.1925, 4.1013) to (10.0444, -25.6)
  arc A3 centre (17.3205, 10) radius 11.5 clockwise from (27.1925, 4.1013) to (17.148, 21.4987)
  arc A4 centre (0, 0) radius 27.5 clockwise from (-17.148, 21.4987) to (17.148, 21.4987)
  arc A5 centre (-17.3205, 10) radius 11.5 clockwise from (-17.148, 21.4987) to (-27.1925, 4.1013)
  arc A6 centre (0, 0) radius 27.5 clockwise from (-10.0444, -25.6) to (-27.1925, 4.1013)
  circle C1 centre (0, 0) radius 27.5
  circle C2 centre (0, 0) radius 27.5
  concentric C1 C2
  dimension "d26" diameter C2 = 55 (= "BearingHolderDiameter")
extrude "Extrude1" new body sketch "Sketch1" along normal blind 3 (= "TopThickness")
sketch "Sketch2" plane through (0, 10.5, 0) normal (0, 1, 0) x axis (-1, 0, 0)
  circle C1 centre (0, 0) radius 27.5
  circle C2 centre (0, -20) radius 4
  circle C3 centre (-17.3205, 10) radius 4
  circle C4 centre (17.3205, 10) radius 4
  point P3 (0, -20)
  point P6 (0, -20)
  point P5 (-17.3205, 10)
  point P7 (-17.3205, 10)
  point P4 (17.3205, 10)
  point P8 (17.3205, 10)
  coincident P3 P6
  coincident P5 P7
  coincident P4 P8
  dimension "d30" diameter C2 = 8 (= "InDiameterBearing")
  dimension "d31" diameter C3 = 8 (= "InDiameterBearing")
  dimension "d32" diameter C4 = 8 (= "InDiameterBearing")
extrude "Extrude2" cut sketch "Sketch2" profile of C2 C3 C4 to an object
sketch "Sketch1" plane through (0, 0, 0) normal (0, 1, 0) x axis (1, 0, 0)
  line L1 (-45, -50) -> (-45, 40)
  line L2 (45, -50) -> (-45, -50)
  line L3 (45, 40) -> (45, -50)
  line L4 (-45, 40) -> (45, 40)
  circle C1 centre (0, 0) radius 28
  point P6 (0, 0)
  point P7 (0, 0)
  point P1 (0, 0)
  vertical L1
  perpendicular L1 L2
  perpendicular L2 L3
  perpendicular L3 L4
  coincident P6 P7
  dimension "d38" distance L4 P6 = 40 (= "PumpTopDistance")
  dimension "d42" distance L1 P6 = 45 (= "PumpWidth / 2")
  dimension "d43" distance P1 L3 = 45 (= "PumpWidth / 2")
  dimension "d44" distance P1 L2 = 50 (= "PumpBottomDistance")
  dimension "d45" diameter C1 = 56 (= "BearingHolderDiameter + GapBeetweenParts")
extrude "Extrude1" new body sketch "Sketch1" along normal blind 7.5 (= "BearingHeight") and against normal blind 6 (= "BaseThickness")
sketch "Sketch5" plane through (0, -6, 0) normal (0, -1, 0) x axis (1, 0, 0)
  line L1 (45, -40) -> (-45, -40)
  line L2 (45, 50) -> (45, -40)
  line L3 (-45, 50) -> (45, 50)
  line L4 (-45, -40) -> (-45, 50)
  circle C1 centre (0, 0) radius 28
work_plane "WorkPlane3" AlongDistance -4.5 (= "-( TubeDiameter / 2 )")
sketch "Sketch6" plane through (0, 3, 5) normal (0, 1, 0) x axis (1, 0, 0)
  line L1 (-29.75, -65) -> (-29.75, 5)
  line L2 (29.75, -65) -> (29.75, 5)
  arc A1 centre (0, 5) radius 29.75 clockwise from (-29.75, 5) to (29.75, 5)
  point P2 (0, 5)
  point P3 (0, 5)
  point P4 (-29.75, 5)
  point P5 (-29.75, -65)
  point P6 (29.75, 5)
  point P7 (29.75, -65)
  coincident P2 P3
  vertical L1
  tangent L1 A1
  tangent L2 A1
  parallel L1 L2
  dimension "d56" diameter A1 = 59.5 (= "BearingHolderDiameter + ( TubeDiameter / 2 )")
  dimension "d57" distance P4 P5 = 70 (= "TubeLengthOutput")
  dimension "d58" distance P6 P7 = 70 (= "TubeLengthOutput")
sketch "Sketch7" plane through (0, 0, 50) normal (0, 0, 1) x axis (1, 0, 0)
  line L1 (45, 7.5) -> (45, -6)
  line L2 (-45, 7.5) -> (45, 7.5)
  line L3 (-45, -6) -> (-45, 7.5)
  line L4 (45, -6) -> (-45, -6)
work_plane "WorkPlane4" sketch "Sketch7" AlongDistance 70
sketch "Sketch10" plane through (0, 1, 70) normal (0, 0, 1) x axis (1, 0, 0)
  line L1 (45, 6.5) -> (45, -7)
  line L2 (-45, 6.5) -> (45, 6.5)
  line L3 (-45, -7) -> (-45, 6.5)
  line L4 (45, -7) -> (-45, -7)
  line L5 (-34.25, 2) -> (-34.25, 6.5)
  line L6 (-25.25, 2) -> (-25.25, 6.5)
  line L7 (-25.25, 6.5) -> (-34.25, 6.5)
  circle C1 centre (-29.75, 2) radius 4.5
  point P2 (-29.75, 2)
  point P3 (-29.75, 2)
  point P8 (-34.25, 6.5)
  point P9 (-34.25, 2)
  point P10 (-25.25, 6.5)
  point P11 (-25.25, 2)
  coincident P2 P3
  coincident L2 P8
  coincident C1 P9
  tangent C1 L5
  coincident L2 P10
  coincident C1 P11
  tangent C1 L6
  parallel L3 L5
  parallel L3 L6
  dimension "d60" diameter C1 = 9 (= "TubeDiameter")
sweep "Sweep1" sketch "Sketch10" TwistAngle 0 TaperAngle 0
sketch "Sketch2" plane through (0, 7.5, 0) normal (0, 1, 0) x axis (-1, 0, 0)
  line L1 (-34.25, 50) -> (-34.25, 0)
  line L2 (-45, 50) -> (-34.25, 50)
  line L3 (-45, -40) -> (-45, 50)
  line L4 (45, -40) -> (-45, -40)
  line L5 (45, 50) -> (45, -40)
  line L6 (34.25, 50) -> (45, 50)
  line L7 (34.25, 0) -> (34.25, 50)
  line L8 (-25.25, 12.1011) -> (-25.25, 50)
  line L9 (25.25, 50) -> (25.25, 12.1011)
  line L10 (-25.25, 50) -> (25.25, 50)
  line L11 (-45, -40) -> (45, -40)
  line L12 (-45, 50) -> (-45, -40)
  line L13 (45, 50) -> (-45, 50)
  line L14 (45, -40) -> (45, 50)
  arc A1 centre (0, 0) radius 34.25 clockwise from (34.25, 0) to (-34.25, 0)
  arc A2 centre (0, 0) radius 28 clockwise from (-25.25, 12.1011) to (25.25, 12.1011)
  circle C1 centre (0, 0) radius 27.5
  point P6 (45, -40)
  point P16 (45, -40)
  point P5 (-45, -40)
  point P17 (-45, -40)
  point P18 (-45, -40)
  point P4 (-45, 50)
  point P19 (-45, 50)
  point P20 (-45, 50)
  point P7 (45, 50)
  point P21 (45, 50)
  point P22 (45, -40)
  point P1 (0, 0)
  point P23 (0, 0)
  coincident P6 P16
  coincident P5 P17
  coincident P5 P18
  coincident P4 P19
  coincident P4 P20
  coincident P7 P21
  coincident P6 P22
  coincident P1 P23
  dimension "d73" diameter C1 = 55 (= "BearingHolderDiameter")
sketch "Sketch1" plane through (0, 7.5, 0) normal (0, 1, 0) x axis (-1, 0, 0)
  line L1 (45, 50) -> (-45, 50)
  line L2 (45, -40) -> (45, 50)
  line L3 (-45, -40) -> (45, -40)
  line L4 (-45, 50) -> (-45, -40)
  circle C1 centre (0, 0) radius 28
  point P1 (0, 0)
  point P6 (0, 0)
  horizontal L1
  vertical L2
  horizontal L3
  vertical L4
  coincident P1 P6
  dimension "d74" diameter C1 = 56 (= "BearingHolderDiameter + GapBeetweenParts")
extrude "Extrude1" new body sketch "Sketch1" along normal blind 3 (= "TopThickness")
extrude "Extrude2" new body sketch "Sketch5" profile of C1 along normal blind 3 (= "MotorDiameterHeight")
sketch "Sketch12" plane through (0, -9, 0) normal (0, -1, 0) x axis (1, 0, 0)
  line L1 (45, -40) -> (-45, -40)
  line L2 (45, 50) -> (45, -40)
  line L3 (-45, 50) -> (45, 50)
  line L4 (-45, -40) -> (-45, 50)
  circle C1 centre (0, 0) radius 11
  point P1 (0, 0)
  point P6 (0, 0)
  coincident P1 P6
  dimension "d82" diameter C1 = 22 (= "MotorDiameter")
extrude "Extrude3" cut sketch "Sketch12" profile of C1 no distance stored
sketch "Sketch13" plane through (0, 7.5, 0) normal (0, 1, 0) x axis (-1, 0, 0)
  line L1 (-25.25, 12.1011) -> (-25.25, 50)
  line L2 (25.25, 50) -> (25.25, 12.1011)
  line L3 (-25.25, 50) -> (25.25, 50)
  arc A1 centre (0, 0) radius 28 clockwise from (-25.25, 12.1011) to (25.25, 12.1011)
  circle C1 centre (0, 0) radius 31.5
  point P1 (0, 0)
  point P7 (0, 0)
  coincident P1 P7
  dimension "d85" diameter C1 = 63 (= "BearingHolderDiameter + BearingOffset + GapBeetweenParts")
extrude "Extrude4" cut sketch "Sketch13" profile of L1 A1 L2 C1 no distance stored
sketch "Sketch2" plane through (0, 10.5, 0) normal (0, 1, 0) x axis (-1, 0, 0)
  line L1 (45, -40) -> (-45, -40)
  line L2 (45, 50) -> (45, -40)
  line L3 (-45, 50) -> (45, 50)
  line L4 (-45, -40) -> (-45, 50)
  line L5 (45, 28) -> (-45, 28)
  line L6 (-45, 39) -> (45, 39)
  line L7 (0, 50) -> (0, 28)
  line L8 (39, 50) -> (39, -40)
  line L9 (0, 0) -> (0, 39)
  line L10 (45, 19.5) -> (0, 19.5)
  line L11 (0, -28) -> (0, -40)
  line L12 (45, -34) -> (-45, -34)
  line L13 (7.5, 39) -> (7.5, -34)
  line L14 (45, 2.5) -> (7.5, 2.5)
  circle C1 centre (0, 0) radius 28
  circle C2 centre (0, 39) radius 2
  circle C3 centre (39, 39) radius 2
  circle C4 centre (-39, 39) radius 2
  circle C5 centre (39, 0) radius 2
  circle C6 centre (-39, 0) radius 2
  circle C7 centre (39, -34) radius 2
  circle C8 centre (-39, -34) radius 2
  point P7 (-45, 28)
  point P8 (45, 28)
  point P9 (45, 39)
  point P10 (-45, 39)
  point P11 (0, 28)
  point P12 (0, 50)
  point P13 (0, 39)
  point P14 (39, -40)
  point P15 (39, 50)
  point P16 (39, 39)
  point P18 (0, 39)
  point P2 (0, 0)
  point P19 (0, 0)
  point P20 (0, 19.5)
  point P21 (45, 19.5)
  point P24 (0, -40)
  point P25 (0, -28)
  point P26 (-45, -34)
  point P27 (45, -34)
  point P28 (7.5, -34)
  point P29 (7.5, 39)
  point P30 (7.5, 2.5)
  point P31 (45, 2.5)
  coincident L4 P7
  coincident L2 P8
  perpendicular L2 L5
  tangent C1 L5
  coincident L2 P9
  coincident L4 P10
  perpendicular L4 L6
  coincident C1 P11
  midpoint L3 P12
  perpendicular L3 L7
  midpoint L6 L7
  midpoint L6 P13
  coincident L1 P14
  coincident L3 P15
  perpendicular L3 L8
  coincident L8 P16
  coincident L6 P16
  symmetric L7 C3 C4
  coincident P13 P18
  coincident P2 P19
  coincident L9 P20
  coincident L2 P21
  perpendicular L2 L10
  midpoint L9 P20
  symmetric C3 L10 C5
  symmetric C4 L10 C6
  midpoint L1 P24
  coincident C1 P25
  perpendicular L1 L11
  coincident L4 P26
  coincident L2 P27
  perpendicular L2 L12
  midpoint L11 L12
  coincident L12 P28
  coincident L6 P29
  perpendicular L6 L13
  midpoint L13 P30
  coincident L2 P31
  perpendicular L2 L14
  symmetric C3 L14 C7
  symmetric C4 L14 C8
  dimension "d90" diameter C2 = 4 (= "ScrewDiameter")
  dimension "d95" distance L2 L8 = 6
  dimension "d96" diameter C3 = 4 (= "ScrewDiameter")
extrude "Extrude5" cut sketch "Sketch2" profile of C2 C3 C4 C5 C6 C7 C8 to an object Side2Offset 0
sketch "Sketch14" plane through (0, -9, 0) normal (0, -1, 0) x axis (1, 0, 0)
  line L1 (45, -40) -> (-45, -40)
  line L2 (45, 50) -> (45, -40)
  line L3 (-45, 50) -> (45, 50)
  line L4 (-45, -40) -> (-45, 50)
  line L5 (-45, -40) -> (45, -40)
  line L6 (-45, 50) -> (-45, -40)
  line L7 (45, 50) -> (-45, 50)
  line L8 (45, -40) -> (45, 50)
  circle C1 centre (0, 0) radius 11
  circle C2 centre (-39, 39) radius 2
  circle C3 centre (-39, 0) radius 2
  circle C4 centre (-39, -34) radius 2
  circle C5 centre (39, -34) radius 2
  circle C6 centre (39, 0) radius 2
  circle C7 centre (39, 39) radius 2
  circle C8 centre (0, 39) radius 2
  circle C9 centre (-39, -33.75) radius 3.5
  circle C10 centre (-39, 0) radius 3.5
  circle C11 centre (-39, 39) radius 3.5
  circle C12 centre (0, 39) radius 3.5
  circle C13 centre (39, 39) radius 3.5
  circle C14 centre (39, 0) radius 3.5
  circle C15 centre (39, -34) radius 3.5
  circle C16 centre (-39, 0) radius 2
  circle C17 centre (0, 39) radius 2
  circle C18 centre (39, 0) radius 2
  circle C19 centre (39, -34) radius 2
  circle C20 centre (-39, 39) radius 2
  circle C21 centre (39, 39) radius 2
  circle C22 centre (-39, -34) radius 2
  circle C23 centre (39, -34) radius 2
  circle C24 centre (0, 0) radius 28
  concentric C2 C11
  concentric C8 C12
  concentric C7 C13
  concentric C6 C14
  concentric C5 C15
  dimension "d97" diameter C9 = 7 (= "ScrewHeadDiameter")
  dimension "d98" diameter C10 = 7 (= "ScrewHeadDiameter")
  dimension "d99" diameter C11 = 7 (= "ScrewHeadDiameter")
  dimension "d100" diameter C12 = 7 (= "ScrewHeadDiameter")
  dimension "d101" diameter C13 = 7 (= "ScrewHeadDiameter")
  dimension "d102" diameter C14 = 7 (= "ScrewHeadDiameter")
  dimension "d103" diameter C15 = 7 (= "ScrewHeadDiameter")
extrude "Extrude3" cut sketch "Sketch2" profile of C2 C3 C4 C5 C6 C7 C8 to an object
sketch "Sketch3" plane through (0, 10.5, 0) normal (0, 1, 0) x axis (-1, 0, 0)
extrude "Extrude6" cut sketch "Sketch14" profile of C2 C3 C4 C5 C6 C7 C8 C9 C10 C11 C12 C13 C14 C15 no distance stored
sketch "Sketch5" plane through (0, 0, 0) normal (0, 0, 1) x axis (1, 0, 0)
  curve K1 (-26.3959, 0) -> (-25.25, 3)
  line L1 (-25.25, 3) -> (-25.25, 7.5)
  curve K2 (-27.5, -0.8971) -> (-26.3959, 0)
  line L2 (-27.5, 7.4622) -> (-27.5, -0.8971)
  line L3 (-25.25, 7.5) -> (-27.5, 7.4622)
  point P6 (-27.5, -0.8971)
  point P7 (-27.5, -0.8971)
  point P4 (-25.25, 7.5)
  point P9 (-25.25, 7.5)
  coincident P6 P7
  vertical L2
  coincident P4 P9
revolve "Revolve1" sketch "Sketch5" AlongAngle 360
sketch "Sketch15" plane through (0, 10.5, 0) normal (0, 1, 0) x axis (-1, 0, 0)
  line L1 (45, -40) -> (-45, -40)
  line L2 (45, 50) -> (45, -40)
  line L3 (-45, 50) -> (45, 50)
  line L4 (-45, -40) -> (-45, 50)
  circle C1 centre (0, 0) radius 28
  circle C2 centre (-39, 0) radius 2
  circle C3 centre (39, -34) radius 2
  circle C4 centre (0, 39) radius 2
  circle C5 centre (-39, 39) radius 2
  circle C6 centre (39, 0) radius 2
  circle C7 centre (39, 39) radius 2
  circle C8 centre (-39, -34) radius 2
sketch "Sketch6" plane through (0, 7.5, 0) normal (0, 1, 0) x axis (-1, 0, 0)
  line L1 (21.4502, -13.321) -> (0, 0)
  arc A1 centre (0, 0) radius 25.25 clockwise from (-11.1946, -22.6328) to (-25.25, 0)
  arc A2 centre (0, -20) radius 11.5 clockwise from (-11.1946, -22.6328) to (11.1946, -22.6328)
  arc A3 centre (0, 0) radius 25.25 clockwise from (25.25, 0) to (11.1946, -22.6328)
  arc A4 centre (17.3205, 10) radius 11.5 clockwise from (25.1979, 1.6216) to (14.0033, 21.0112)
  arc A5 centre (-17.3205, 10) radius 11.5 clockwise from (-14.0033, 21.0112) to (-25.1979, 1.6216)
  circle C1 centre (0, 0) radius 25.25
  circle C2 centre (0, 0) radius 18.25
  circle C3 centre (15.5036, -9.6281) radius 2
  circle C4 centre (0.5863, 18.2406) radius 2
  circle C5 centre (-16.09, -8.6125) radius 2
  arc A6 centre (0, 0) radius 25.25 clockwise from (-14.0033, 21.0112) to (14.0033, 21.0112)
  arc A7 centre (0, 0) radius 25.25 clockwise from (-25.25, 0) to (-25.1979, 1.6216)
  arc A8 centre (0, 0) radius 25.25 clockwise from (25.1979, 1.6216) to (25.25, 0)
  point P4 (0, 0)
  point P13 (0, 0)
  point P14 (21.4502, -13.321)
  point P16 (15.5036, -9.6281)
  concentric A1 C1
  coincident P4 P13
  midpoint A3 P14
  coincident C2 P16
  coincident L1 P16
  dimension "d112" diameter C3 = 4 (= "ScrewDiameter")
  dimension "d114" C-Pattern1-Angle = 360
extrude "Extrude5" cut sketch "Sketch6" profile of C3 C4 C5 to an object Side2Offset 0
sketch "Sketch7" plane through (0, -6, 0) normal (0, -1, 0) x axis (1, 0, 0)
  circle C1 centre (-0.5863, 18.2406) radius 2
  circle C2 centre (-15.5036, -9.6281) radius 2
  circle C3 centre (16.09, -8.6125) radius 2
  circle C4 centre (-0.5863, 18.2406) radius 2
  circle C5 centre (-15.5036, -9.6281) radius 2
  circle C6 centre (16.09, -8.6125) radius 2
  circle C7 centre (-0.5863, 18.2406) radius 3.5
  circle C8 centre (16.09, -8.6125) radius 3.5
  circle C9 centre (-15.5036, -9.6281) radius 3.5
  circle C10 centre (0, 0) radius 27.5
  concentric C4 C7
  concentric C3 C8
  concentric C2 C9
  dimension "d123" diameter C7 = 7 (= "ScrewHeadDiameter")
  dimension "d124" diameter C8 = 7 (= "ScrewHeadDiameter")
  dimension "d125" diameter C9 = 7 (= "ScrewHeadDiameter")
extrude "Extrude6" cut sketch "Sketch7" profile of C1 C2 C3 C4 C5 C6 C7 C8 C9 no distance stored
sketch "Sketch8" plane through (0, 7.5, 0) normal (0, 1, 0) x axis (-1, 0, 0)
sketch "Sketch10" plane through (0, -6, 0) normal (0, -1, 0) x axis (1, 0, 0)
  line L1 (7, 0) -> (-4.7156, 0.0813)
  line L2 (7.0247, -2.5488) -> (-3.0249, -2.4791)
  line L3 (1.4451, 2.04) -> (-1.4166, 2.0599)
  circle C1 centre (0, 0) radius 2.5
  point P1 (0, 0)
  point P2 (0, 0)
  point P7 (-1.4166, 2.0599)
  point P8 (1.4451, 2.04)
  coincident P1 P2
  parallel L1 L2
  tangent C1 L2
  parallel L2 L3
  coincident C1 P7
  coincident C1 P8
  dimension "d133" diameter C1 = 5 (= "ShaftDiameter")
  dimension "d134" distance L2 L3 = 4.55 (= "ShaftNotchDistance")
extrude "Extrude7" cut sketch "Sketch10" profile of C1 L3 no distance stored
